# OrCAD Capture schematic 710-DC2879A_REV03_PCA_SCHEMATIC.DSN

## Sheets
1 PAGE3: size A
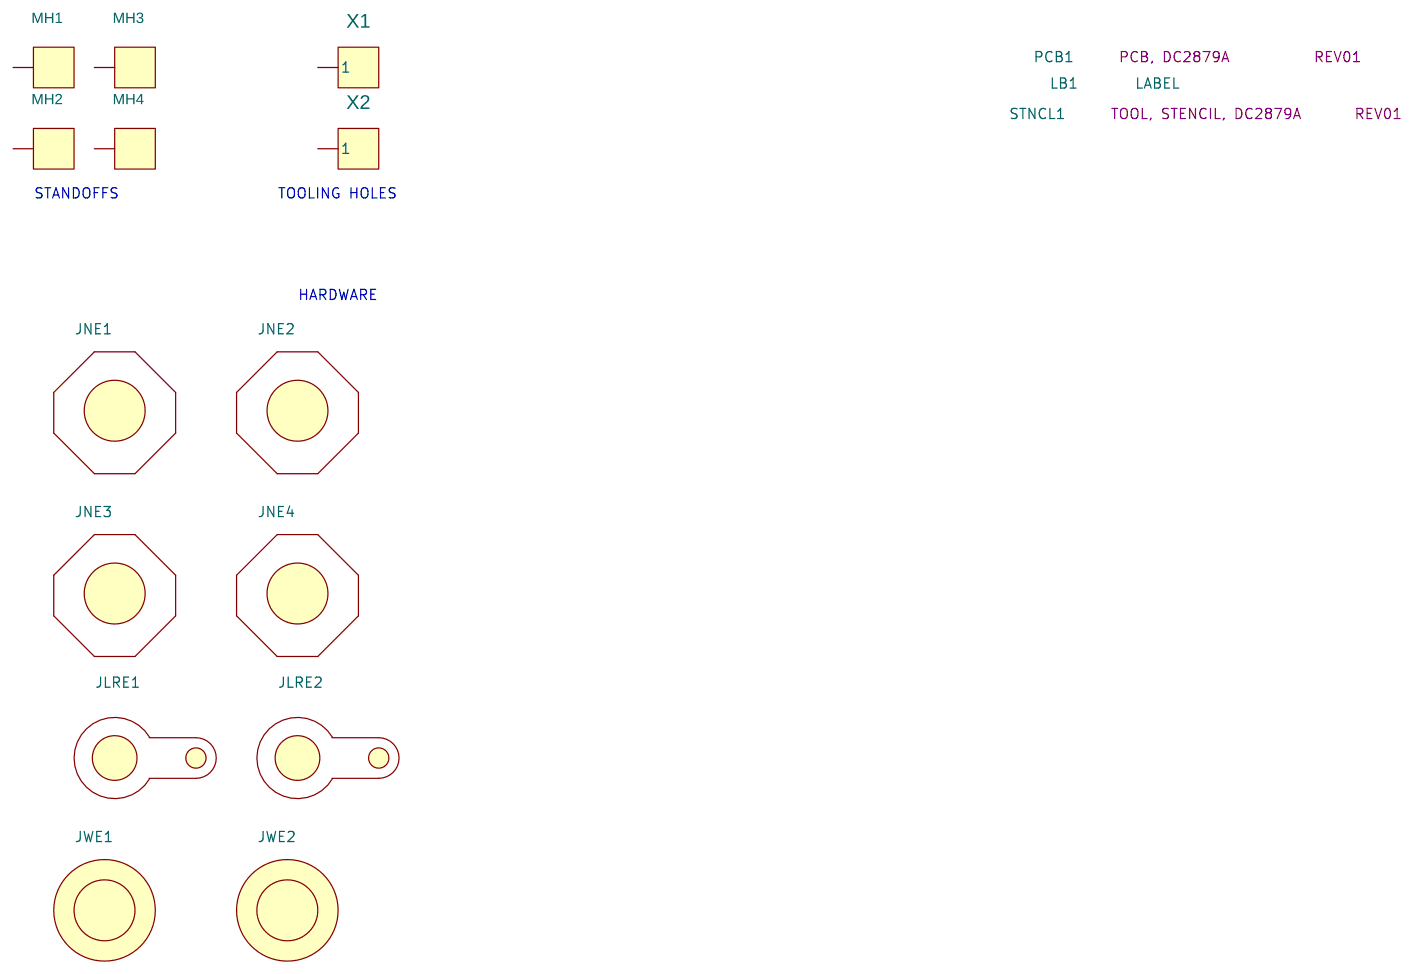
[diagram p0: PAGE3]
2 PAGE2: size Custom; company: ANALOG DEVICES; note: DEMO BOARD BILL OF MATERIALS; note: 72V 300W STEP-DOWN    MODULE     REGULATOR
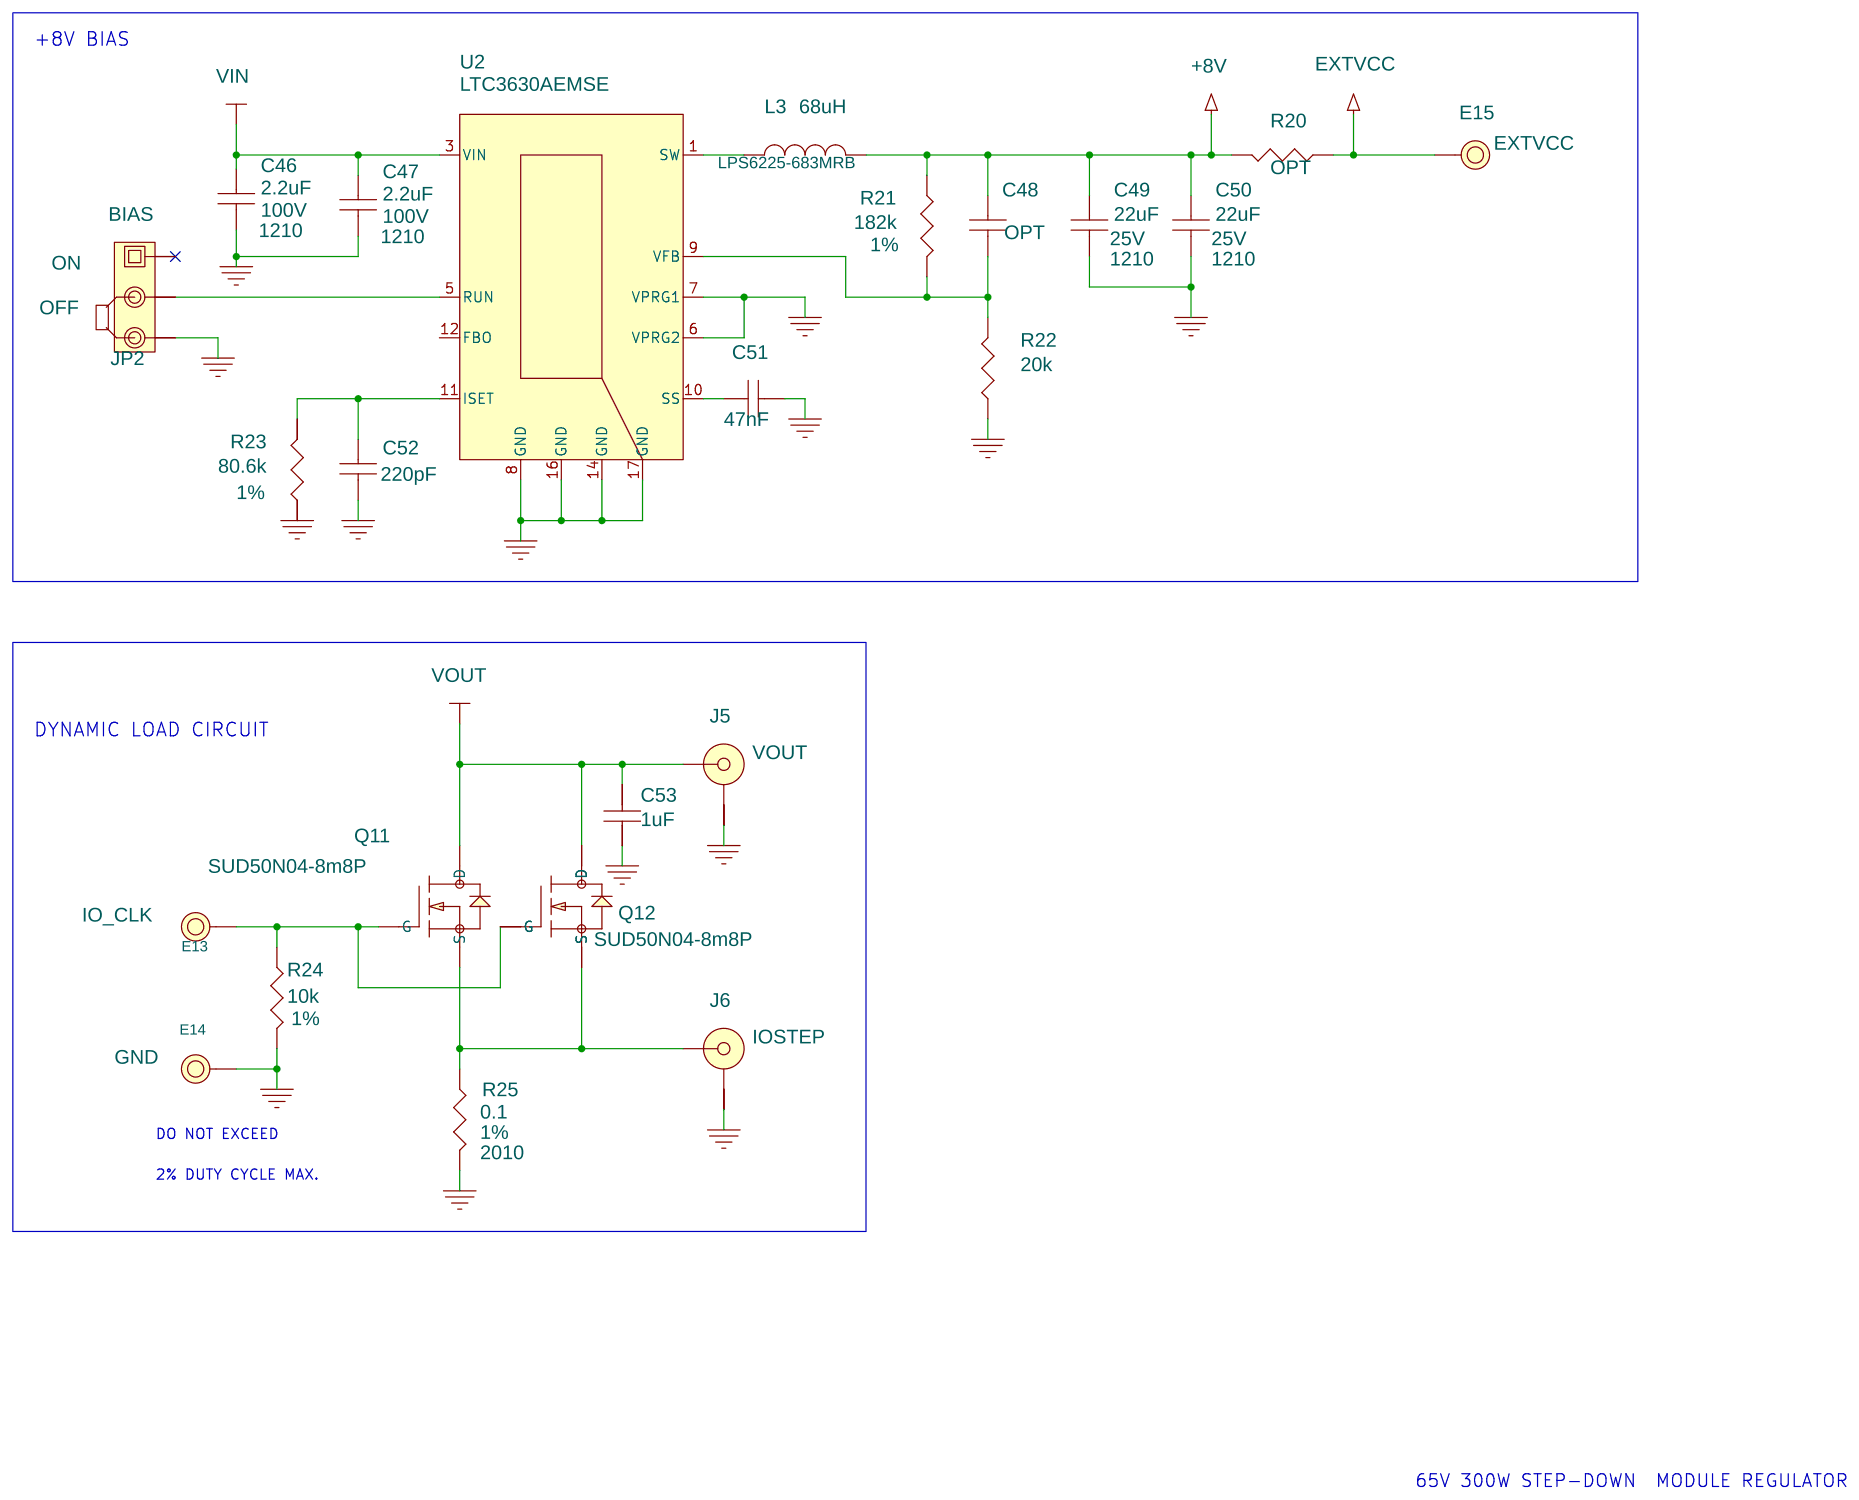
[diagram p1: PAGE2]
3 PAGE1: size Custom; company: ANALOG DEVICES; note: DEMO BOARD BILL OF MATERIALS; note: 65V 300W STEP-DOWN  MODULE REGULATOR
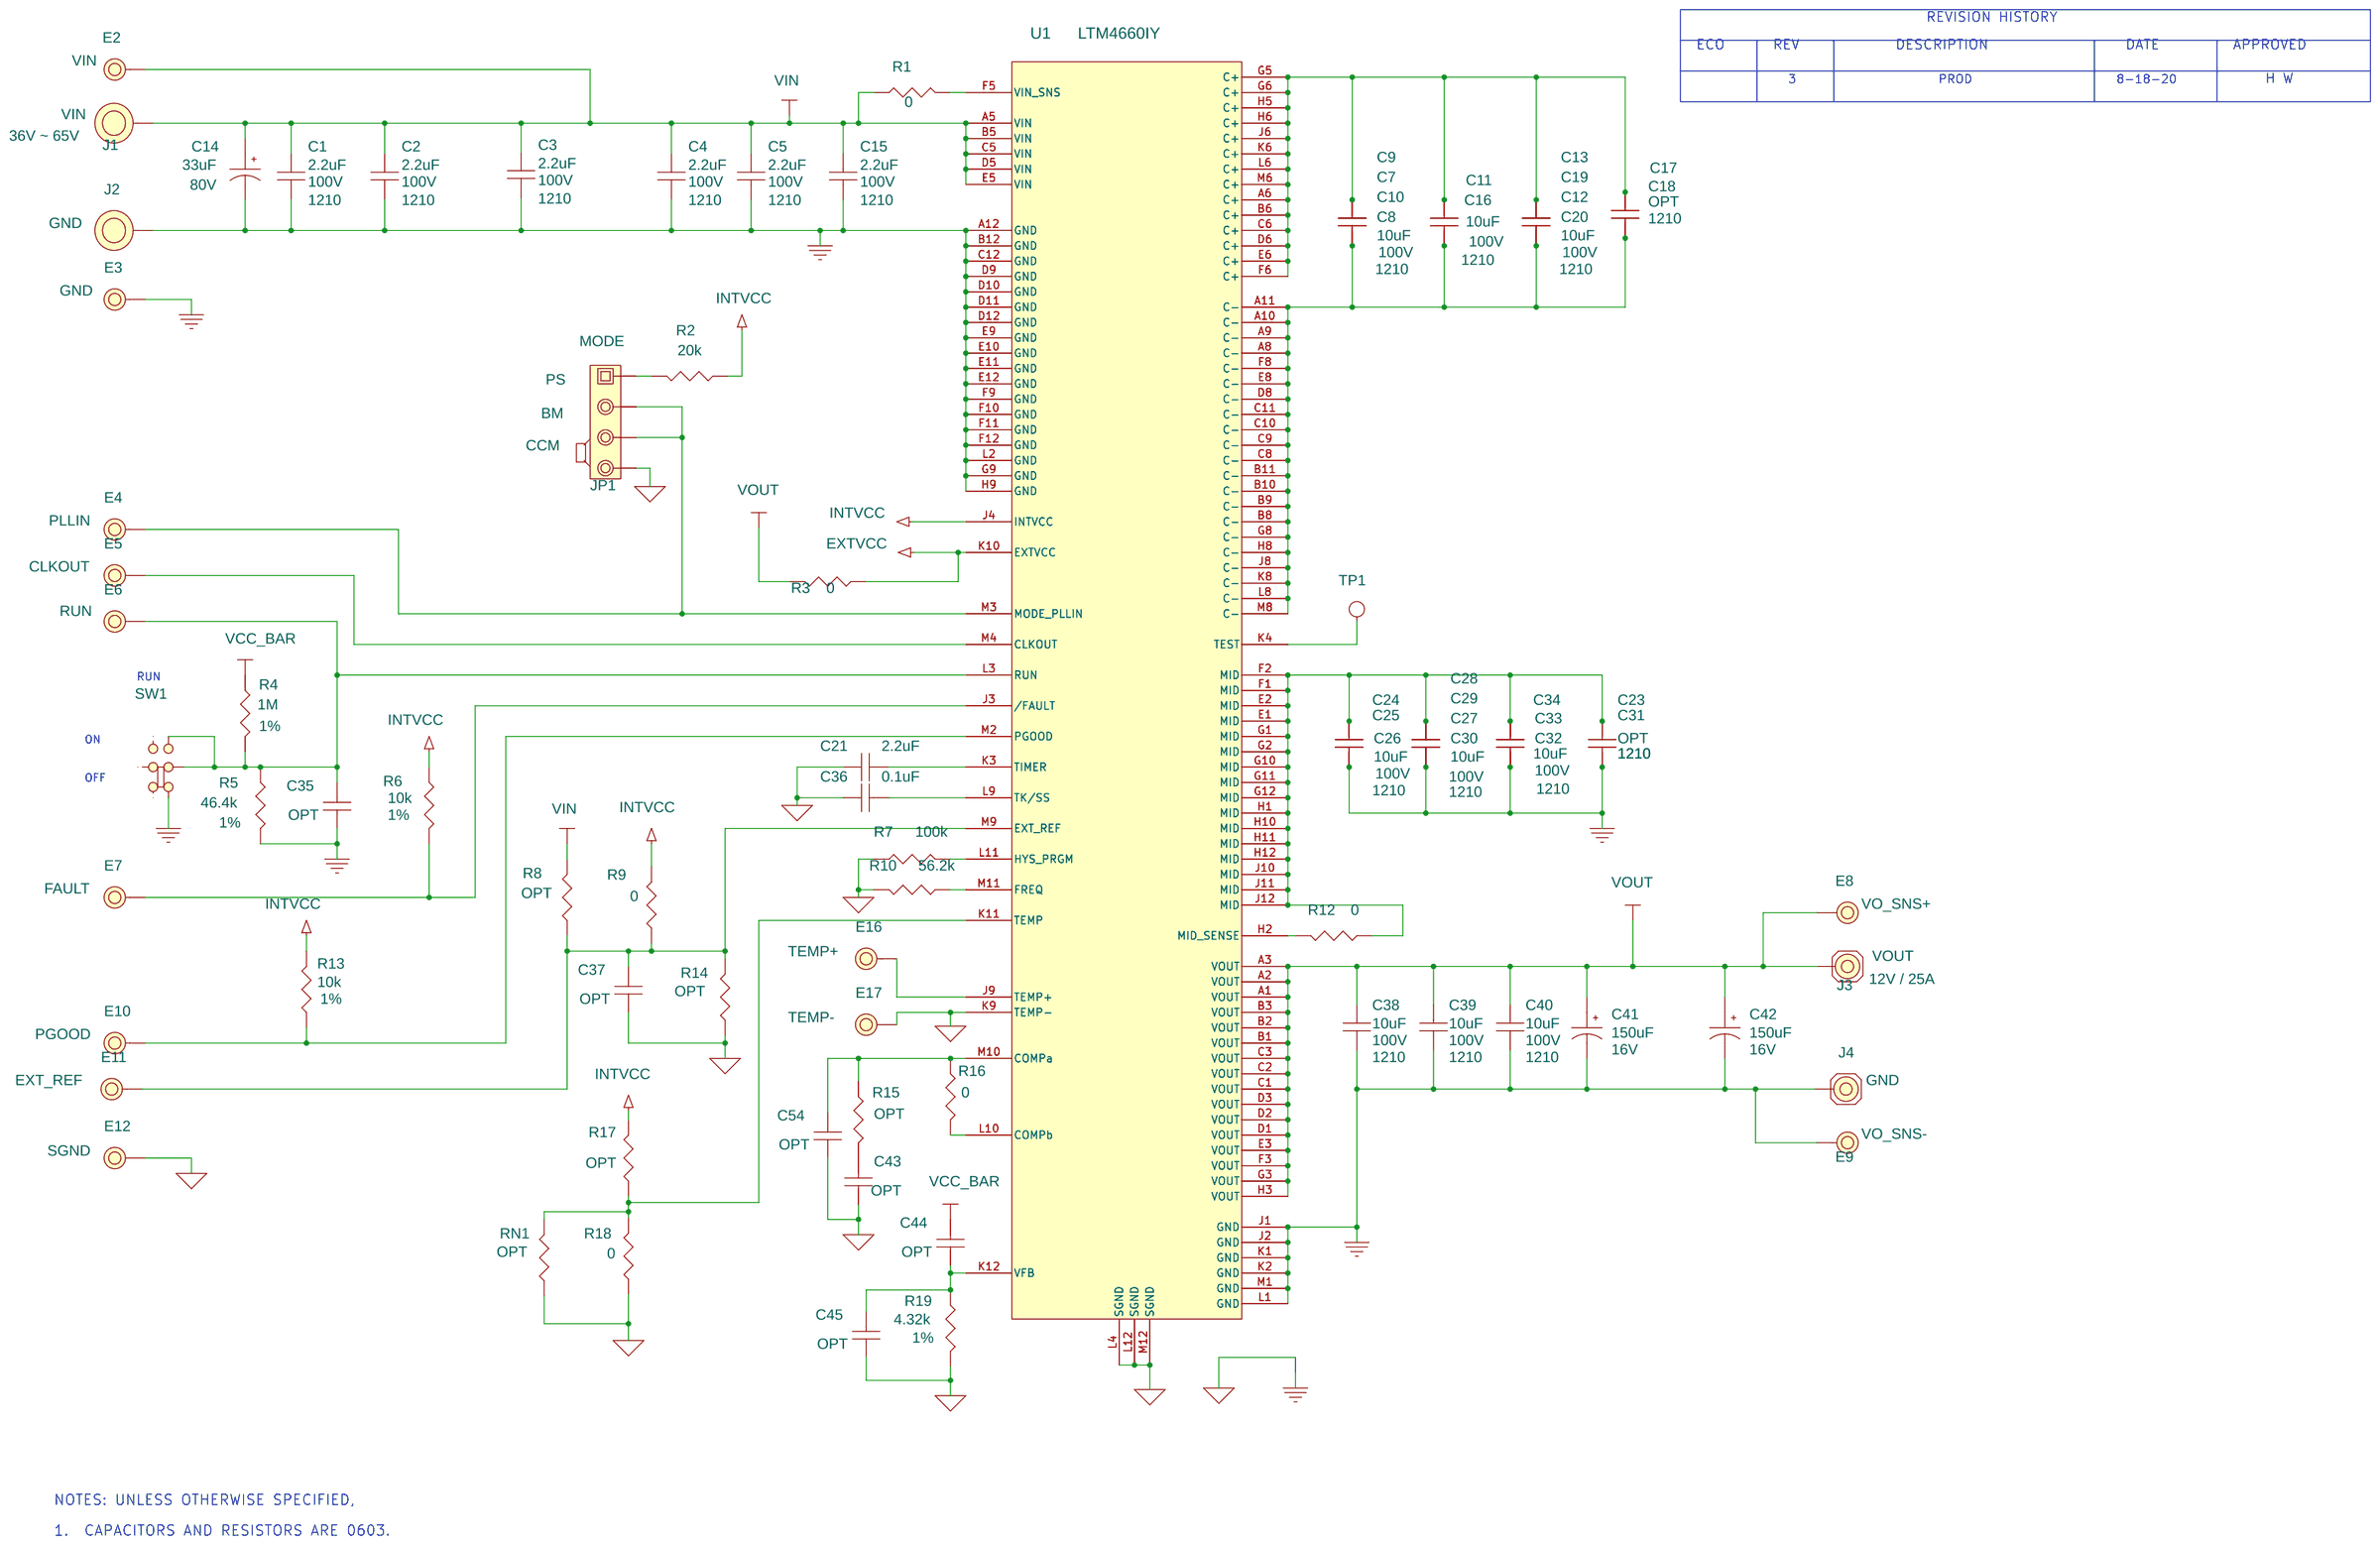
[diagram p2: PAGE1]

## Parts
sheet PAGE1
C1  2.2uF  [CC1210N]
C2  2.2uF  [CC1210N]
C3  2.2uF  [CC1210N]
C4  2.2uF  [CC1210N]
C5  2.2uF  [CC1210N]
C7  10uF  [CC1210N]
C8  10uF  [CC1210N]
C9  10uF  [CC1210N]
C10  10uF  [CC1210N]
C11  10uF  [CC1210N]
C12  10uF  [CC1210N]
C13  10uF  [CC1210N]
C14  33uF  [CAP\SANYO\10X10.2\CE]
C15  2.2uF  [CC1210N]
C16  10uF  [CC1210N]
C17  OPT  [CC1210N]
C18  OPT  [CC1210N]
C19  10uF  [CC1210N]
C20  10uF  [CC1210N]
C21  2.2uF  [CC0603N]
C23  OPT  [CC1210N]
C24  10uF  [CC1210N]
C25  10uF  [CC1210N]
C26  10uF  [CC1210N]
C27  10uF  [CC1210N]
C28  10uF  [CC1210N]
C29  10uF  [CC1210N]
C30  10uF  [CC1210N]
C31  OPT  [CC1210N]
C32  10uF  [CC1210N]
C33  10uF  [CC1210N]
C34  10uF  [CC1210N]
C35  OPT  [CC0603N]
C36  0.1uF  [CC0603N]
C37  OPT  [CC0603N]
C38  10uF  [CC1210N]
C39  10uF  [CC1210N]
C40  10uF  [CC1210N]
C41  150uF  [CAP\SANYO\SVPA_E7]
C42  150uF  [CAP\SANYO\SVPA_E7]
C43  OPT  [CC0603N]
C44  OPT  [CC0603N]
C45  OPT  [CC0603N]
C54  OPT  [CC0603N]
E2  TEST POINT  [MILLMAX2501]
E3  TEST POINT  [MILLMAX2501]
E4  TEST POINT  [MILLMAX2501]
E5  TEST POINT  [MILLMAX2501]
E6  TEST POINT  [MILLMAX2501]
E7  TEST POINT  [MILLMAX2501]
E8  TEST POINT  [MILLMAX2501]
E9  TEST POINT  [MILLMAX2501]
E10  TEST POINT  [MILLMAX2501]
E11  TEST POINT  [MILLMAX2501]
E12  TEST POINT  [MILLMAX2501]
E16  TEST POINT  [MILLMAX2501]
E17  TEST POINT  [MILLMAX2501]
J1  BANANA JACK  [KEY-575-4]
J2  BANANA JACK  [KEY-575-4]
J3  STUD, FASTENER, #10-32  [PENN-KFH-032]
J4  STUD, FASTENER, #10-32  [PENN-KFH-032]
JP1  HDR  [HD1X4-079,JP4X1/079]
R1  0  [CR0603N]
R2  20k  [CR0603N]
R3  0  [CR0603N]
R4  1M  [CR0603N]
R5  46.4k  [CR0603N]
R6  10k  [CR0603N]
R7  100k  [CR0603N]
R8  OPT  [CR0603N]
R9  0  [CR0603N]
R10  56.2k  [CR0603N]
R12  0  [CR0603N]
R13  10k  [CR0603N]
R14  OPT  [CR0603N]
R15  OPT  [CR0603N]
R16  0  [CR0603N]
R17  OPT  [CR0603N]
R18  0  [CR0603N]
R19  4.32k  [CR0603N]
RN1  OPT  [CR0603N]
SW1  DPDT  [C&K-JS202011CQN]
TP1  TEST  [TEST-PADS]
U1  LTM4660IY  [LTC-BGA-120-1623]
XJP1  SHUNT
sheet PAGE2
C46  2.2uF  [CC1210N]
C47  2.2uF  [CC1210N]
C48  OPT  [CC0603N]
C49  22uF  [CC1210N]
C50  22uF  [CC1210N]
C51  47nF  [CC0603N]
C52  220pF  [CC0603N]
C53  1uF  [CC0603N]
E13  TEST POINT  [MILLMAX2501]
E14  TEST POINT  [MILLMAX2501]
E15  TEST POINT  [MILLMAX2501]
J5  RF, BNC  [CONNEX-112404]
J6  RF, BNC  [CONNEX-112404]
JP2  HDR  [HD1X3-079]
L3  68uH  [COILCRAFT-LPS6225]
Q11  SUD50N04-8m8P  [TO-252-3N]
Q12  SUD50N04-8m8P  [TO-252-3N]
R20  OPT  [CR0603N]
R21  182k  [CR0603N]
R22  20k  [CR0603N]
R23  80.6k  [CR0603N]
R24  10k  [CR0603N]
R25  0.1  [CR2010N,CR2010L,CR2010M]
U2  LTC3630AEMSE  [LTC-MSE-16-1871]
XJP2  SHUNT
sheet PAGE3
JLRE1  RING, LUG, CRIMP
JLRE2  RING, LUG, CRIMP
JNE1  NUT,HEX
JNE2  NUT,HEX
JNE3  NUT,HEX
JNE4  NUT,HEX
JWE1  WASHER
JWE2  WASHER
LB1  LABEL  [895-0154_REV01]
MH1  STANDOFF  [KEYSTONE_8829-8834]
MH2  STANDOFF  [KEYSTONE_8829-8834]
MH3  STANDOFF  [KEYSTONE_8829-8834]
MH4  STANDOFF  [KEYSTONE_8829-8834]
PCB1  PCB, DC2879A
STNCL1  700-DC2879A
X1  CON1  [TOOL\ALGNHL\70]
X2  CON1  [TOOL\ALGNHL\70]

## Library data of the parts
C1-C5 C15 C46 C47 = CAP: CAP.,2.2uF,X7R,100V,10%,1210; CLASS: DISCRETE; Dielectric Type: X7R; FPLIST: CC1210N,CC1210L,CC1210M; Manufacturer: MURATA; Manufacturer PN: GRM32DR72A225KA12K; PART_NUMBER: 150-2506; Package Size: 1210; Part Number: MURATA GRM32DR72A225KA12K; Rated Voltage: 100V; Tolerance: 10%
C7 C16 C19 C25 C29 C38-C40 = CAP: CAP.,10uF,X7R,50V,10%,1210, NO SUBS. ALLOWED; CLASS: DISCRETE; Dielectric Type: X7R; FPLIST: CC1210N,CC1210L,CC1210M; Manufacturer: MURATA; Manufacturer PN: GRM32ER71H106KA12L; PART_NUMBER: 150-3043; Package Size: 1210; Package Type: SMD; Part Number: MURATA GRM32ER71H106KA12L; Rated Voltage: 100V; Tolerance: 10%; UserField01: NO SUBS. ALLOWED
C8-C10 C12 C13 C20 C24 C26-C28 C30 C32 C33 = CAP: CAP.,10uF,X7R,50V,10%,1210, NO SUBS. ALLOWED; CLASS: DISCRETE; Dielectric Type: X7R; FPLIST: CC1210N,CC1210L,CC1210M; Manufacturer: MURATA; Manufacturer PN: GRM32ER71H106KA12L; PART_NUMBER: 150-3043; Package Size: 1210; Package Type: SMD; Part Number: MURATA GRM32ER71H106KA12L; Rated Voltage: 50V; Tolerance: 10%; UserField01: NO SUBS. ALLOWED
C11 = CAP: CAP.,10uF,X7R,50V,10%,1210, NO SUBS. ALLOWED; CLASS: DISCRETE; Dielectric Type: X7R; FPLIST: CC1210N,CC1210L,CC1210M; Manufacturer: MURATA; Manufacturer PN: GRM32ER71H106KA12L; PART_NUMBER: 150-3043; Package Size: 1210; Package Type: 1210; Part Number: MURATA GRM32ER71H106KA12L; Rated Voltage: 50V; Tolerance: 10%; UserField01: NO SUBS. ALLOWED
C14 = CAP_P: CAP.,33uF,ALUM. ELECT.,80V,20%,10x10.2mm SMD, RADIAL,AEC-Q200; CLASS: DISCRETE; Dielectric Type: ALUM. ELECT.; Manufacturer: PANASONIC; Manufacturer PN: EEHZA1K330P; PART_NUMBER: 150-2503; Package Size: 10x10.2mm SMD, RADIAL; Part Number: PANASONIC EEHZA1K330P; Rated Voltage: 80V; Tolerance: 20%
C17 C18 C23 C31 = CAP: CAP., OPTION, 1210; CLASS: DISCRETE; FPLIST: CC1210N,CC1210L,CC1210M; PART_NUMBER: 150-3035; Package Size: 1210; Package Type: SMD; Part Number: MURATA GRM32ER71H106KA12L; UserField01: NO SUBS. ALLOWED
C21 = CAP: CAP.,2.2uF,X7S,25V,10%,0603; CLASS: DISCRETE; Dielectric Type: X7S; FPLIST: CC0603N,CC0603L,CC0603M; Inventory Qty: 4000; Manufacturer: MURATA; Manufacturer PN: GRM188C71E225KE11D; PART_NUMBER: 150-1812; Package Size: 0603; Part Number: MURATA GRM188R61E105KA12D; Rated Voltage: 25V; Temperature Coefficient: X7S; Tolerance: 10%
C34 = CAP: CAP.,10uF,X7R,50V,10%,1210, NO SUBS. ALLOWED; CLASS: DISCRETE; Dielectric Type: X7R; FPLIST: CC1210N,CC1210L,CC1210M; Manufacturer: MURATA; Manufacturer PN: GRM32ER71H106KA12L; PART_NUMBER: 150-3043; Package Size: 1210; Package Type: 1210; Part Number: MURATA GRM32ER71H106KA12L; Rated Voltage: 100V; Tolerance: 10%; UserField01: NO SUBS. ALLOWED
C35 C37 C43-C45 C48 C54 = CAP: CAP., OPTION, 0603; CLASS: DISCRETE; FPLIST: CC0603N,CC0603L,CC0603M; PART_NUMBER: 150-3038; Package Size: 0603; Package Type: SMD; Part Number: OPTION; UserField01: OPTION
C36 = CAP: CAP.,0.1uF,X7S,100V,10%,0603; CLASS: DISCRETE; Dielectric Type: X7S; FPLIST: CC0603N,CC0603L,CC0603M; Manufacturer: TDK; Manufacturer PN: C1608X7S2A104K080AB; PART_NUMBER: 150-0493; Package Size: 0603; Part Number: MURATA GRM188R72A104KA35D; Rated Voltage: 100V; Tolerance: 10%
C41 C42 = CAP_P: CAP.,150uF,ALUM./OS-CON,16V,20%,8x6.9mm SMD, RADIAL; CLASS: DISCRETE; Dielectric Type: ALUM./OS-CON; Manufacturer: PANASONIC; Manufacturer PN: 16SVPC150M; PART_NUMBER: 150-2273; Package Size: 8x6.9mm SMD, RADIAL; Part Number: PANASONIC 16SVPC150M; Rated Voltage: 16V; Tolerance: 20%
E2 = TESTPOINT_.219_MILL-MAX_2501: TEST POINT,TURRET,0.094",MTG. HOLE; CLASS: IO; Label1: VIN; Label2: 14V MAX; Manufacturer: MILL-MAX; Manufacturer PN: 2501-2-00-80-00-00-07-0; PART_NUMBER: 260-0003; Part Number: MILL-MAX 2501-2-00-80-00-00-07-0
E3 = TESTPOINT_.219_MILL-MAX_2501: TEST POINT,TURRET,0.094",MTG. HOLE; CLASS: IO; Label1: GND; Label2: 14V MAX; Manufacturer: MILL-MAX; Manufacturer PN: 2501-2-00-80-00-00-07-0; PART_NUMBER: 260-0003; Part Number: MILL-MAX 2501-2-00-80-00-00-07-0
E4 = TESTPOINT_.219_MILL-MAX_2501: TEST POINT,TURRET,0.094",MTG. HOLE; CLASS: IO; Label1: PLLIN; Label2: 14V MAX; Manufacturer: MILL-MAX; Manufacturer PN: 2501-2-00-80-00-00-07-0; PART_NUMBER: 260-0003; Part Number: MILL-MAX 2501-2-00-80-00-00-07-0
E5 = TESTPOINT_.219_MILL-MAX_2501: TEST POINT,TURRET,0.094",MTG. HOLE; CLASS: IO; Label1: CLKOUT; Label2: 14V MAX; Manufacturer: MILL-MAX; Manufacturer PN: 2501-2-00-80-00-00-07-0; PART_NUMBER: 260-0003; Part Number: MILL-MAX 2501-2-00-80-00-00-07-0
E6 = TESTPOINT_.219_MILL-MAX_2501: TEST POINT,TURRET,0.094",MTG. HOLE; CLASS: IO; Label1: RUN; Label2: 14V MAX; Manufacturer: MILL-MAX; Manufacturer PN: 2501-2-00-80-00-00-07-0; PART_NUMBER: 260-0003; Part Number: MILL-MAX 2501-2-00-80-00-00-07-0
E7 = TESTPOINT_.219_MILL-MAX_2501: TEST POINT,TURRET,0.094",MTG. HOLE; CLASS: IO; Label1: FAULT; Label2: 14V MAX; Manufacturer: MILL-MAX; Manufacturer PN: 2501-2-00-80-00-00-07-0; PART_NUMBER: 260-0003; Part Number: MILL-MAX 2501-2-00-80-00-00-07-0
E8 = TESTPOINT_.219_MILL-MAX_2501: TEST POINT,TURRET,0.094",MTG. HOLE; CLASS: IO; Label1: VO_SNS+; Label2: 14V MAX; Manufacturer: MILL-MAX; Manufacturer PN: 2501-2-00-80-00-00-07-0; PART_NUMBER: 260-0003; Part Number: MILL-MAX 2501-2-00-80-00-00-07-0
E9 = TESTPOINT_.219_MILL-MAX_2501: TEST POINT,TURRET,0.094",MTG. HOLE; CLASS: IO; Label1: VO_SNS-; Label2: 14V MAX; Manufacturer: MILL-MAX; Manufacturer PN: 2501-2-00-80-00-00-07-0; PART_NUMBER: 260-0003; Part Number: MILL-MAX 2501-2-00-80-00-00-07-0
E10 = TESTPOINT_.219_MILL-MAX_2501: TEST POINT,TURRET,0.094",MTG. HOLE; CLASS: IO; Label1: PGOOD; Label2: 14V MAX; Manufacturer: MILL-MAX; Manufacturer PN: 2501-2-00-80-00-00-07-0; PART_NUMBER: 260-0003; Part Number: MILL-MAX 2501-2-00-80-00-00-07-0
E11 = TESTPOINT_.219_MILL-MAX_2501: TEST POINT,TURRET,0.094",MTG. HOLE; CLASS: IO; Label1: EXT_REF; Label2: 14V MAX; Manufacturer: MILL-MAX; Manufacturer PN: 2501-2-00-80-00-00-07-0; PART_NUMBER: 260-0003; Part Number: MILL-MAX 2501-2-00-80-00-00-07-0
E12 = TESTPOINT_.219_MILL-MAX_2501: TEST POINT,TURRET,0.094",MTG. HOLE; CLASS: IO; Label1: SGND; Label2: 14V MAX; Manufacturer: MILL-MAX; Manufacturer PN: 2501-2-00-80-00-00-07-0; PART_NUMBER: 260-0003; Part Number: MILL-MAX 2501-2-00-80-00-00-07-0
E16 = TESTPOINT_.219_MILL-MAX_2501: TEST POINT,TURRET,0.094",MTG. HOLE; CLASS: IO; Label1: TEMP+; Label2: 14V MAX; Manufacturer: MILL-MAX; Manufacturer PN: 2501-2-00-80-00-00-07-0; PART_NUMBER: 260-0003; Part Number: MILL-MAX 2501-2-00-80-00-00-07-0
E17 = TESTPOINT_.219_MILL-MAX_2501: TEST POINT,TURRET,0.094",MTG. HOLE; CLASS: IO; Label1: TEMP-; Label2: 14V MAX; Manufacturer: MILL-MAX; Manufacturer PN: 2501-2-00-80-00-00-07-0; PART_NUMBER: 260-0003; Part Number: MILL-MAX 2501-2-00-80-00-00-07-0
J1 = BANANA_KEYSTONE-575-4: CONN.,BANANA JACK,FEMALE,THT,NON-INSULATED, SWAGE; CLASS: IO; Label1: VIN; Label2: 36V ~ 65V; Manufacturer: KEYSTONE; Manufacturer PN: 575-4; PART_NUMBER: 250-0428; Part Number: KEYSTONE 575-4
J2 = BANANA_KEYSTONE-575-4: CONN.,BANANA JACK,FEMALE,THT,NON-INSULATED, SWAGE; CLASS: IO; Label1: GND; Manufacturer: KEYSTONE; Manufacturer PN: 575-4; PART_NUMBER: 250-0428; Part Number: KEYSTONE 575-4
J3 = PEM-KFH: 10th Part Field: 12V / 25A; 9th Part Field: VOUT; CLASS: DISCRETE; Manufacturer: PENNENGINEERING; Manufacturer PN: KFH-032-10ET; PART_NUMBER: 769-0005; Part Number: PEM KFH-032-10
J4 = PEM-KFH: 9th Part Field: GND; CLASS: DISCRETE; Manufacturer: PENNENGINEERING; Manufacturer PN: KFH-032-10ET; PART_NUMBER: 769-0005; Part Number: PEM KFH-032-10
JP1 = HDR1X4_ALT1: CONN.,HDR,MALE,1x4,2mm,STR, THT; 10th Part Field: BM; 12th Part Field: CCM; 13tht Part Field: MODE; 9th Part Field: PS; CLASS: IO; Manufacturer: WURTH ELEKTRONIK; Manufacturer PN: 62000411121; PART_NUMBER: 250-0563
R1 = RES: RES.,0 OHM,1/10W,0603; CLASS: DISCRETE; FPLIST: CR0603N,CR0603L,CR0603M; Manufacturer: VISHAY; Manufacturer PN: CRCW06030000Z0EA; PART_NUMBER: 100-0009; Package Size: 0603; Part Number: VISHAY CRCW06030000Z0EA; Rated Power: 1/10W
R2 R22 = RES: RES.,AEC-Q200,20k OHMS,5%,1/10W,0603; CLASS: DISCRETE; FPLIST: CR0603N,CR0603L,CR0603M; Manufacturer: VISHAY; Manufacturer PN: CRCW060320K0JNEA; PART_NUMBER: 100-0160; Package Size: 0603; Part Number: VISHAY CRCW060320K0JNEA; Rated Power: 1/10W; Temperature Coefficient: 200ppm/C; Tolerance: 5%
R3 = RES: RES.,0 OHM,1/10W,0603,AEC-Q200; CLASS: DISCRETE; FPLIST: CR0603N,CR0603L,CR0603M; Inventory Qty: 698116; Manufacturer: VISHAY; Manufacturer PN: CRCW06030000Z0EA; PART_NUMBER: 100-0009; Package Size: 0603; Part Number: OPTION; Rated Power: 1/10W
R4 = RES: RES.,AEC-Q200,1M OHM,1%,1/10W,0603; CLASS: DISCRETE; FPLIST: CR0603N,CR0603L,CR0603M; Manufacturer: NIC; Manufacturer PN: NRC06F1004TRF; PART_NUMBER: 100-0119; Package Size: 0603; Part Number: VISHAY CRCW08051M00FKEA; Rated Power: 1/10W; Temperature Coefficient: 100ppm/C; Tolerance: 1%
R5 = RES: RES.,46.4k OHMS,1%,1/10W,0603; CLASS: DISCRETE; FPLIST: CR0603N,CR0603L,CR0603M; Manufacturer: NIC; Manufacturer PN: NRC06F4642TRF; PART_NUMBER: 100-2595; Package Size: 0603; Rated Power: 1/10W; Temperature Coefficient: 100ppm/C; Tolerance: 1%
R6 R13 = RES: RES.,AEC-Q200,10k OHMS,1%,1/10W,0603; CLASS: DISCRETE; FPLIST: CR0603N,CR0603L,CR0603M; Manufacturer: VISHAY; Manufacturer PN: CRCW060310K0FKEA; PART_NUMBER: 100-2012; Package Size: 0603; Part Number: VISHAY CRCW060310K0FKEA; Rated Power: 1/10W; Temperature Coefficient: +/-100ppm/C; Tolerance: 1%
R7 = RES: RES.,100k OHMS,1%,1/10W,0603; CLASS: DISCRETE; FPLIST: CR0603N,CR0603L,CR0603M; Manufacturer: VISHAY; Manufacturer PN: CRCW0603100KFKEA; PART_NUMBER: 100-0343; Package Size: 0603; Part Number: VISHAY CRCW0603100KFKEA; Rated Power: 1/10W; Temperature Coefficient: +/-100ppm; Tolerance: 1%
R8 R14 R15 = RES: RES., OPTION, 0603; CLASS: DISCRETE; FPLIST: CR0603N,CR0603L,CR0603M; PART_NUMBER: 100-2374; Package Size: 0603
R9 R12 R16 R18 = RES: RES.,AEC-Q200,0 OHM,1/10W,0603; CLASS: DISCRETE; FPLIST: CR0603N,CR0603L,CR0603M; Manufacturer: VISHAY; Manufacturer PN: CRCW06030000Z0EA; PART_NUMBER: 100-0009; Package Size: 0603; Rated Power: 1/10W
R10 = RES: RES.,56.2k OHMS,1%,1/10W,0603,AEC-Q200; CLASS: DISCRETE; FPLIST: CR0603N,CR0603L,CR0603M; Inventory Qty: 20019; Manufacturer: NIC; Manufacturer PN: NRC06F5622TRF; PART_NUMBER: 100-2697; Package Size: 0603; Rated Power: 1/10W; Temperature Coefficient: 100ppm/C; Tolerance: 1%
R17 R20 = RES: RES., OPTION, 0603; CLASS: DISCRETE; FPLIST: CR0603N,CR0603L,CR0603M; PART_NUMBER: 100-2374; Package Size: 0603; Part Number: OPTION
R19 = RES: RES.,AEC-Q200,4.32k OHMS,1%,1/10W,0603; CLASS: DISCRETE; FPLIST: CR0603N,CR0603L,CR0603M; Manufacturer: VISHAY; Manufacturer PN: CRCW06034K32FKEA; PART_NUMBER: 100-0038; Package Size: 0603; Part Number: VISHAY CRCW06034K32FKEA; Rated Power: 1/10W; Temperature Coefficient: 100ppm/C; Tolerance: 1%
RN1 = THERMISTOR-GENERAL: THERMISTOR, OPTION, 0603; CLASS: DISCRETE; FPLIST: CR0603N,CR0603L,CR0603M; PART_NUMBER: 122-0005; Package Size: 0603
SW1 = SW-SLD-SPDT: SWITCH,SLIDE,DPDT,0.3A,6VDC,PTH; CLASS: DISCRETE; Manufacturer: C&K; Manufacturer PN: JS202011CQN; PART_NUMBER: 430-0039; Part Number: C&K JS202011CQN
TP1 = E-100SMT: NONE; Part Number: NONE
U1 = LTM4660-BGA: IC,HYBRID STEP-DOWN NON-ISOLATED uMODULE BUS CONVERTER; CLASS: IC; Manufacturer: ANALOG DEVICES INC.; Manufacturer PN: LTM4660IY#PBF; PART_NUMBER: LTM4660IY#PBF; Package Type: BGA-120
XJP1 XJP2 = SHUNT_2MM: CONN.,SHUNT,FEMALE,2 POS,2mm; CLASS: IO; Manufacturer: Wurth Elektronik; Manufacturer PN: 60800213421; PART_NUMBER: 250-0485
C49 C50 = CAP: CAP.,22uF,X5R,25V,10%,1210; CLASS: DISCRETE; Dielectric Type: X5R; FPLIST: CC1210N,CC1210L,CC1210M; Manufacturer: MURATA; Manufacturer PN: GRM32ER61E226KE15L; PART_NUMBER: 150-3033; Package Size: 1210; Package Type: SMD; Part Number: MURATA GRM32ER61E226KE15L; Rated Voltage: 25V; Tolerance: 10%
C51 = CAP: CAP.,0.047uF,X7R,25V,10%,0603; CLASS: DISCRETE; Dielectric Type: X7R; FPLIST: CC0603N,CC0603L,CC0603M; Manufacturer: MURATA; Manufacturer PN: GRM188R71E473KA01D; PART_NUMBER: 150-0063; Package Size: 0603; Part Number: MURATA GRM188R71E473KA01D; Rated Voltage: 25V; Tolerance: 10%
C52 = CAP: CAP.,220pF,C0G,50V,5%,0603; CLASS: DISCRETE; Dielectric Type: C0G; FPLIST: CC0603N,CC0603L,CC0603M; Manufacturer: MURATA; Manufacturer PN: GRM1885C1H221JA01D; PART_NUMBER: 150-0031; Package Size: 0603; Part Number: MURATA GRM1885C1H221JA01J; Rated Voltage: 50V; Tolerance: 5%
C53 = CAP: CAP.,1uF,X7R,25V,10%,0603,AEC-Q200; CLASS: DISCRETE; Dielectric Type: X7R; FPLIST: CC0603N,CC0603L,CC0603M; Manufacturer: TDK; Manufacturer PN: CGA3E1X7R1E105K080AC; PART_NUMBER: 150-0291; Package Size: 0603; Part Number: MURATA GRM188R61E105KA12D; Rated Voltage: 25V; Tolerance: 10%
E13 = TESTPOINT_.219_MILL-MAX_2501: TEST POINT,TURRET,0.094",MTG. HOLE; 1st Part Field: IO_CLK; CLASS: IO; FPLIST: MILLMAX2501,MILLMAX2501_ALT1; Manufacturer: MILL-MAX; Manufacturer PN: 2501-2-00-80-00-00-07-0; PART_NUMBER: 260-0003; Part Number: MILL-MAX 2501-2-00-80-00-00-07-0
E14 = TESTPOINT_.219_MILL-MAX_2501: TEST POINT,TURRET,0.094",MTG. HOLE; 1st Part Field: GND; CLASS: IO; FPLIST: MILLMAX2501,MILLMAX2501_ALT1; Manufacturer: MILL-MAX; Manufacturer PN: 2501-2-00-80-00-00-07-0; PART_NUMBER: 260-0003; Part Number: MILL-MAX 2501-2-00-80-00-00-07-0
E15 = TESTPOINT_.219_MILL-MAX_2501: TEST POINT,TURRET,0.094",MTG. HOLE; CLASS: IO; Label1: EXTVCC; Label2: 14V MAX; Manufacturer: MILL-MAX; Manufacturer PN: 2501-2-00-80-00-00-07-0; PART_NUMBER: 260-0003; Part Number: MILL-MAX 2501-2-00-80-00-00-07-0
J5 = BNC_50_OHM_112404_B: CONN.,RF, BNC,RCPT JACK,5-PIN,STR, THT,50 Ohms; 1st Part Field: VOUT; CLASS: IO; Manufacturer: AMPHENOL RF; Manufacturer PN: 112404; PART_NUMBER: 250-0427; Part Number: CONNEX 112404
J6 = BNC_50_OHM_112404_B: CONN.,RF, BNC,RCPT JACK,5-PIN,STR, THT,50 Ohms; 1st Part Field: IOSTEP; CLASS: IO; Manufacturer: AMPHENOL RF; Manufacturer PN: 112404; PART_NUMBER: 250-0427; Part Number: CONNEX 112404
JP2 = 1X3_A: CONN.,HDR,MALE,1x3,2mm,THT, STR,NO SUBS. ALLOWED; 11th Part Field: OFF; 12th Part Field: BIAS; 9th Part Field: ON; CLASS: IO; Manufacturer: Wurth Elektronik; Manufacturer PN: 62000311121; PART_NUMBER: 250-0639
L3 = IND: IND.,68uH,PWR, SHIELDED,20%,0.62A,0.42 OHM,6mmX6mm SMD; 1st Part Field: LPS6225-683MRB; CLASS: DISCRETE; Manufacturer: Coilcraft; Manufacturer PN: LPS6225-683MRB; PART_NUMBER: 200-0477; Package Size: 6mmX6mm SMD; Part Number: COILCRAFT LPS6225-683MRB; Tolerance: 20%
Q11 Q12 = 3P_N-CH_TYPE2A: XSTR.,MOSFET, N-CH,40V,TO-252 (DPAK); CLASS: DISCRETE; FPLIST: TO-252-3N,TO-252-3L,TO-252-3M; Manufacturer: VISHAY; Manufacturer PN: SUD50N04-8M8P-4GE3; PART_NUMBER: 240-0021; Package Type: TO-252 (DPAK); Part Number: VISHAY SILICONIX SUD50N04-8M8P-4GE3; Rated Voltage: 40V
R21 = RES: RES.,AEC-Q200,182k OHMS,1%,1/10W,0603; CLASS: DISCRETE; FPLIST: CR0603N,CR0603L,CR0603M; Manufacturer: PANASONIC; Manufacturer PN: ERJ3EKF1823V; PART_NUMBER: 100-2770; Package Size: 0603; Part Number: PANASONIC ERJ3EKF1823V; Rated Power: 1/10W; Temperature Coefficient: 100ppm/C; Tolerance: 1%
R23 = RES: RES.,80.6k OHMS,1%,1/10W,0603; CLASS: DISCRETE; FPLIST: CR0603N,CR0603L,CR0603M; Manufacturer: VISHAY; Manufacturer PN: CRCW060380K6FKEA; PART_NUMBER: 100-2503; Package Size: 0603; Part Number: VISHAY CRCW060380K6FKEA; Rated Power: 1/10W; Temperature Coefficient: 100ppm/C; Tolerance: 1%
R24 = RES: RES.,AEC-Q200,10k OHMS,1%,1/10W,0603; CLASS: DISCRETE; FPLIST: CR0603N,CR0603L,CR0603M; Manufacturer: VISHAY; Manufacturer PN: CRCW060310K0FKEA; PART_NUMBER: 100-2012; Package Size: 0603; Rated Power: 1/10W; Temperature Coefficient: +/-100ppm/C; Tolerance: 1%
R25 = RES: RES.,0.1 OHM,1%,1W,2010; CLASS: DISCRETE; Manufacturer: VISHAY; Manufacturer PN: WSL2010R1000FEA18; PART_NUMBER: 100-0994; Package Size: 2010; Rated Power: 1W; Temperature Coefficient: 100PPM; Tolerance: 1%
U2 = LTC3630A-MSE: IC, SYNCHRONOUS STEP-DOWN CONVERTER; CLASS: IC; Manufacturer: LINEAR TECH.; Manufacturer PN: LTC3630AEMSE#TRPBF; PART_NUMBER: LTC3630AEMSE#PBF; Package Size: MSE16; Part Number: LINEAR TECH. LTC3630AEMSE
JLRE1 JLRE2 = Lug_Ring: RING, LUG, CRIMP,#10,NON-INSULATED,SOLDERLESS TERMINALS; CLASS: DISCRETE; Manufacturer: KEYSTONE; Manufacturer PN: 8205; PART_NUMBER: 769-0010; Part Number: KEYSTONE 8205
JNE1-JNE4 = NUT: NUT,HEX,#10-32,BRASS; CLASS: DISCRETE; Manufacturer: PENCOM; Manufacturer PN: NU1132; PART_NUMBER: 761-0013; Part Number: ANY #10-32
JWE1 JWE2 = Washer: WASHER,#10,LOCK,EXT,TIN FINISH; CLASS: DISCRETE; Manufacturer: PENCOM; Manufacturer PN: WA4526; PART_NUMBER: 762-0021; Part Number: ANY #10 EXT BZ TN
LB1 = BLANK_LABEL: LABEL SPEC, DEMO BOARD SERIAL NUMBER; Manufacturer: BRADY; Manufacturer PN: THT-96-717-10; PART_NUMBER: 895-0154
MH1-MH4 = MP-PINNED: STANDOFF,NYLON,SNAP-ON,0.625"; CLASS: DISCRETE; Manufacturer: KEYSTONE; Manufacturer PN: 8834; PART_NUMBER: 763-0013; Part Number: KEYSTONE_8833
PCB1 = BLANK_PCB_PART: BOM Notes: REV01; CLASS: DISCRETE; Manufacturer: SUN ELECTRONIC INDUSTRIES CORP; Manufacturer PN: 600-DC2879A_REV01; PART_NUMBER: 600-DC2879A
STNCL1 = BLANK_STENCIL_PART: TOOL, STENCIL, DC2879A; BOM Notes: REV01; CLASS: DISCRETE; Manufacturer: Linear Technology; Manufacturer PN: 830-DC2879A; PART_NUMBER: 830-DC2879A
X1 X2 = CON1: DO NOT STUFF; Part Number: PADS ONLY

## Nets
+8V: C48.1 C49.1 C50.1 L3.2 R20.1 R21.2
GND: C1.2 C2.2 C3.2 C4.2 C5.2 C14.2 C15.2 C23.2 C24.2 C25.2 C26.2 C27.2 C28.2 C29.2 C30.2 C31.2 C32.2 C33.2 C34.2 C35.1 C38.2 C39.2 C40.2 C41.2 C42.2 C46.2 C47.2 C49.2 C50.2 C51.2 C52.2 C53.1 E3.1 E9.1 E14.1 J2.1 J4.1 J5.2 J5.3 J5.4 J5.5 J6.2 J6.3 J6.4 J6.5 JP2.3 R5.2 R22.1 R23.2 R24.2 R25.2 SW1.3 U1.A12(GND) U1.B12(GND) U1.C12(GND) U1.D9(GND) U1.D10(GND) U1.D11(GND) U1.D12(GND) U1.E9(GND) U1.E10(GND) U1.E11(GND) U1.E12(GND) U1.F9(GND) U1.F10(GND) U1.F11(GND) U1.F12(GND) U1.G9(GND) U1.H9(GND) U1.J1(GND) U1.J2(GND) U1.K1(GND) U1.K2(GND) U1.L1(GND) U1.L2(GND) U1.M1(GND) U2.6(VPRG2) U2.7(VPRG1) U2.8(GND) U2.14(GND) U2.16(GND) U2.17(GND)
GND_SIGNAL: C21.1 C36.1 C37.1 C43.1 C45.1 C54.1 E12.1 E17.1 JP1.4 R7.2 R10.2 R14.2 R18.2 R19.2 RN1.1 U1.K9(TEMP-) U1.L4(SGND) U1.L12(SGND) U1.M12(SGND)
VIN: C1.1 C2.1 C3.1 C4.1 C5.1 C14.1 C15.1 C46.1 C47.1 E2.1 J1.1 R1.2 R4.1 R8.1 U1.A5(VIN) U1.B5(VIN) U1.C5(VIN) U1.D5(VIN) U1.E5(VIN) U2.3(VIN)
EXTVCC: E15.1 R3.2 R20.2 U1.K10(EXTVCC)
INTVCC: R2.2 R6.1 R9.2 R13.1 R17.1 U1.J4(INTVCC)
VOUT: C38.1 C39.1 C40.1 C41.1 C42.1 C44.2 C53.2 E8.1 J3.1 J5.1 Q11.2(D) Q12.2(D) R3.1 U1.A1(VOUT) U1.A2(VOUT) U1.A3(VOUT) U1.B1(VOUT) U1.B2(VOUT) U1.B3(VOUT) U1.C1(VOUT) U1.C2(VOUT) U1.C3(VOUT) U1.D1(VOUT) U1.D2(VOUT) U1.D3(VOUT) U1.E3(VOUT) U1.F3(VOUT) U1.G3(VOUT) U1.H3(VOUT)
N139306: C7.2 C8.2 C9.2 C10.2 C11.2 C12.2 C13.2 C16.2 C17.2 C18.2 C19.2 C20.2 U1.A8(C-) U1.A9(C-) U1.A10(C-) U1.A11(C-) U1.B8(C-) U1.B9(C-) U1.B10(C-) U1.B11(C-) U1.C8(C-) U1.C9(C-) U1.C10(C-) U1.C11(C-) U1.D8(C-) U1.E8(C-) U1.F8(C-) U1.G8(C-) U1.H8(C-) U1.J8(C-) U1.K8(C-) U1.L8(C-) U1.M8(C-)
N139310: C7.1 C8.1 C9.1 C10.1 C11.1 C12.1 C13.1 C16.1 C17.1 C18.1 C19.1 C20.1 U1.A6(C+) U1.B6(C+) U1.C6(C+) U1.D6(C+) U1.E6(C+) U1.F6(C+) U1.G5(C+) U1.G6(C+) U1.H5(C+) U1.H6(C+) U1.J6(C+) U1.K6(C+) U1.L6(C+) U1.M6(C+)
N141010: C23.1 C24.1 C25.1 C26.1 C27.1 C28.1 C29.1 C30.1 C31.1 C32.1 C33.1 C34.1 R12.2 U1.E1(MID) U1.E2(MID) U1.F1(MID) U1.F2(MID) U1.G1(MID) U1.G2(MID) U1.G10(MID) U1.G11(MID) U1.G12(MID) U1.H1(MID) U1.H10(MID) U1.H11(MID) U1.H12(MID) U1.J10(MID) U1.J11(MID) U1.J12(MID)
N141583: R12.1 U1.H2(MID_SENSE)
N144217: R1.1 U1.F5(VIN_SNS)
N146447: C37.2 E11.1 R8.2 R9.1 R14.1 U1.M9(EXT_REF)
N146531: C35.2 E6.1 R4.2 R5.1 SW1.1 SW1.2 U1.L3(RUN)
N146535: E4.1 JP1.2 JP1.3 U1.M3(MODE_PLLIN)
N146585: E7.1 R6.2 U1.J3(/FAULT)
N146589: E10.1 R13.2 U1.M2(PGOOD)
N146659: E5.1 U1.M4(CLKOUT)
N146873: JP1.1 R2.1
N146893: C21.2 U1.K3(TIMER)
N146929: C36.2 U1.L9(TK/SS)
N149369: R16.1 U1.L10(COMPb)
N149516: R7.1 U1.L11(HYS_PRGM)
N149924: R10.1 U1.M11(FREQ)
N150764: R17.2 R18.1 RN1.2 U1.K11(TEMP)
N154382: C54.2 R15.2 R16.2 U1.M10(COMPa)
N155447: C44.1 C45.2 R19.1 U1.K12(VFB)
N156581: E13.1 Q11.1(G) Q12.1(G) R24.1
N156601: J6.1 Q11.3(S) Q12.3(S) R25.1
N157579: C52.1 R23.1 U2.11(ISET)
N157583: C51.1 U2.10(SS)
N157591: C48.2 R21.1 R22.2 U2.9(VFB)
N157835: L3.1 U2.1(SW)
N165559: TP1.1(A) U1.K4(TEST)
N178912: JP2.2 U2.5(RUN)
N16615638: E16.1 U1.J9(TEMP+)
N16637629: C43.2 R15.1

Not connected (* = marked no-connect by the designer): JP2 1*; MH1 1; MH2 1; MH3 1; MH4 1; SW1 4 5 6; U2 12(FBO); X1 1; X2 1

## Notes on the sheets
sheet 1
- STANDOFFS
- TOOLING HOLES
- HARDWARE
sheet 2
- +8V BIAS
- DYNAMIC LOAD CIRCUIT
- DO NOT EXCEED
- 2% DUTY CYCLE MAX.
- 65V 300W STEP-DOWN  MODULE REGULATOR
sheet 3
- REVISION HISTORY
- ECO
- REV
- DESCRIPTION
- DATE
- APPROVED
- 3
- PROD
- 8-18-20
- H W
- RUN
- ON
- OFF
- NOTES: UNLESS OTHERWISE SPECIFIED,
- 1.  CAPACITORS AND RESISTORS ARE 0603.
